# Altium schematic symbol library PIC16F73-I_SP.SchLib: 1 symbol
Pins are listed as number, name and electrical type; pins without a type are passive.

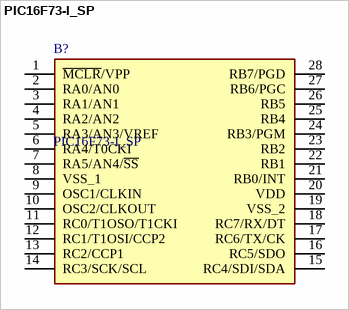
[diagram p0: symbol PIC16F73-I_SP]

## PIC16F73-I_SP
designator B?
8-bit CMOS FLASH Microcontrollers; Manufacturer_Name: Microchip; Manufacturer_Part_Number: PIC16F73-I/SP; Geometry.Height: 4.06mm
footprint DIP794W56P254L3467H406Q28N
pins: 1 ~{MCLR}/VPP, 2 RA0/AN0, 3 RA1/AN1, 4 RA2/AN2, 5 RA3/AN3/VREF, 6 RA4/T0CKI, 7 RA5/AN4/~{SS}, 8 VSS_1, 9 OSC1/CLKIN, 10 OSC2/CLKOUT, 11 RC0/T1OSO/T1CKI, 12 RC1/T1OSI/CCP2, 13 RC2/CCP1, 14 RC3/SCK/SCL, 15 RC4/SDI/SDA, 16 RC5/SDO, 17 RC6/TX/CK, 18 RC7/RX/DT, 19 VSS_2, 20 VDD, 21 RB0/INT, 22 RB1, 23 RB2, 24 RB3/PGM, 25 RB4, 26 RB5, 27 RB6/PGC, 28 RB7/PGD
